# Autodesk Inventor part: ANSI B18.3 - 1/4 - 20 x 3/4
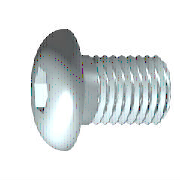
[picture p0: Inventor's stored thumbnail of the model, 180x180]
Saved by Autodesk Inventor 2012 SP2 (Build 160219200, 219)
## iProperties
Created: 2011-02
Part Number: ANSI B18.3 - 1/4 - 20 x 3/4
Material: Steel, Mild
Description: Hexagon Socket Button Head Cap Screw
Document SubType Name: Modeling
Standard: ANSI B18.3
Designer: Philip S. Pinto
Standard Revision: 2003
Standards Organization: ANSI
Language: en-US
Size Designation: 1/4 - 20 x 3/4
Categories: <MemberInstance><Categories><Category DisplayName="Fasteners" InternalName="e4da775c-781d-43d5-af7c-5136215cf5a6" Mnemonic="FSTN"><Category DisplayName="Bolts"
Density: 1 g/cm^3
IsCustomPart: 0
Author: Philip S. Pinto
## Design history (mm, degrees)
workplane "Work Plane1"
fillet "Fillet2" dims "d30" = 0.1 (= R)
revolve "Body" stored, may be unused: angle "d10" = 90 deg
sketch "Sketch2"
  geometry: L1 (0, -7.77)-(0, 7.77) reference; L2 (-7.77, 0)-(7.77, 0) reference; L3 (2.288, 0)-(1.144, -1.981); L4 (1.144, -1.981)-(-1.144, -1.981); L5 (-1.144, -1.981)-(-2.288, 0); L6 (-2.288, 0)-(-1.144, 1.981); L7 (-1.144, 1.981)-(1.144, 1.981); L8 (1.144, 1.981)-(2.288, 0); 2 further points
  constraints: 12 end point, 1 coincident, 1 horizontal alignment, 1 point on line, 12 other
extrude "Slot" join sketch "Sketch2" stored distance "d11" = 10; taper "d12" = 0 deg
body "Solid1"
fillet "Fillet1" dims "d17" = 2.9718 (= RR)
feature "Thread" dims "d13" = 16.5098 (= GEL), "d14" = 0
chamfer "Chamfer1" distance "d15" = 0.77902 (= -0.5 x SPD + 0.5 x GD); stored, may be unused: second distance "d16" = 0.77902 (= GUL), angle "d27" = 45 deg
sketch "Sketch1"
  geometry: L1 (0.178, 0)-(19.05, 0); L2 (19.05, 0)-(19.05, 3.175); L3 (19.05, 3.175)-(2.54, 3.175); L4 (2.54, 3.175)-(0, 3.175); L5 (0, 3.175)-(0, 3.175); L6 (0, 3.175)-(0, 5.55); L7 (0, 5.55)-(-3.353, 5.55); L8 (-3.353, 5.55)-(-3.353, 2.288); L9 (-3.353, 2.288)-(-1.143, 2.288); L10 (-1.143, 2.288)-(0.178, 0); L11 (-7.833, 0)-(23.531, 0) reference; L12 (0, -1.11)-(0, 6.66) reference; L13 (2.54, 3.175)-(0, 3.175)
  constraints: 22 end point, 6 parallel, 2 collinear, 2 perpendicular, 1 horizontal, 1 point on line
  dimensions: "d1" = 16.5098 distance from line of L3.end L2 (= GEL); "d2" = 2.5401 distance of L4.end L3.end (computed from GAL); "d3" = 3.3528 distance between parallel lines of L8 L6 (= KOH); "d4" = 2.2098 distance of L8.end L9.end (= INTI); "d5" = 60 deg angle of L10 L1; "d6" = 6.35 diameter of L3 L1 (= GD); "d7" = 6.35 diameter of L5 L1 (= BDM); "d8" = 4.57539 diameter of L9 L1 (= 1.1547 x SW); "d9" = 11.0998 diameter of L7 L1 (= KOD); "d26" = 19.05 distance between parallel lines of L12 L2 (= NLG)
other parameters: "GD" = 6.35 (= NND) [user parameter; used in 2 equation terms], "NLG" = 19.05 [user parameter; used in 1 equation term], "GEL" = 16.5098 [user parameter; used in 2 equation terms], "KOD" = 11.0998 [user parameter; used in 1 equation term], "KOH" = 3.3528 [user parameter; used in 1 equation term], "INTI" = 2.2098 [user parameter; used in 1 equation term], "GAL" = 2.54 [user parameter; used in 1 equation term], "GUL" = 0.77902 [user parameter; used in 1 equation term], "BDM" = 6.35 (= NND) [user parameter; used in 1 equation term], "SW" = 3.9624 [user parameter; used in 1 equation term], "RR" = 2.9718 [user parameter; used in 1 equation term], "SPD" = 4.79196 [user parameter; used in 2 equation terms], "d19" = 0, "d28" = 0, "d29" = 0, "R" = 0.1 [user parameter; used in 1 equation term], "TOA" = 30 deg [user parameter], "GD1" = 4.79196 (= SPD) [user parameter], "THREADDIA" = 6.35 [user parameter], "PTC" = 1.27 (computed from TPU) [user parameter], "KOH1" = 0.7874 [user parameter], "NND" = 6.35 [user parameter; used in 2 equation terms], "E0" = 4.57657 [user parameter]
